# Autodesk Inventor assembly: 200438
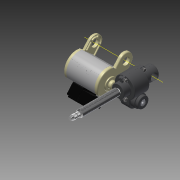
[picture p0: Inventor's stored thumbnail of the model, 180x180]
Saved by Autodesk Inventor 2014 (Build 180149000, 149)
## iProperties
Created: 2008-01
Part Number: 200438
Document SubType Name: Assembly
Designer: jjohnson
Author: jjohnson
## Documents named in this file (4)
- C:\Users\iTools\Desktop\tutorial files\Automotive\2000\200438.iam
- C:\Users\iTools\Desktop\tutorial files\Automotive\2000\201985.iam
- C:\Users\iTools\Desktop\tutorial files\Automotive\2000\203620.iam
- C:\Users\iTools\Desktop\tutorial files\Automotive\2000\206896.iam
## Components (3 placed, 3 different names)
1. 206896:1 [sub-assembly] — Insert:1, Insert:2
2. 201985:1 [sub-assembly] — Insert:1
3. 203620:1 [sub-assembly] — Insert:2
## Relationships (2: Insert 2)
- Insert:1: 206896:1 ↔ 201985:1
- Insert:2: 206896:1 ↔ 203620:1
